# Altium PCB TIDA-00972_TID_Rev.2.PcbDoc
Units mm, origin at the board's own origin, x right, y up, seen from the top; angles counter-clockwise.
Board outline 8.12 x 16.23 mm, 2 copper layers (Top Layer, Bottom Layer), stack 1.575 mm thick; 15 components, 7 nets, 38 pads, 12 vias.
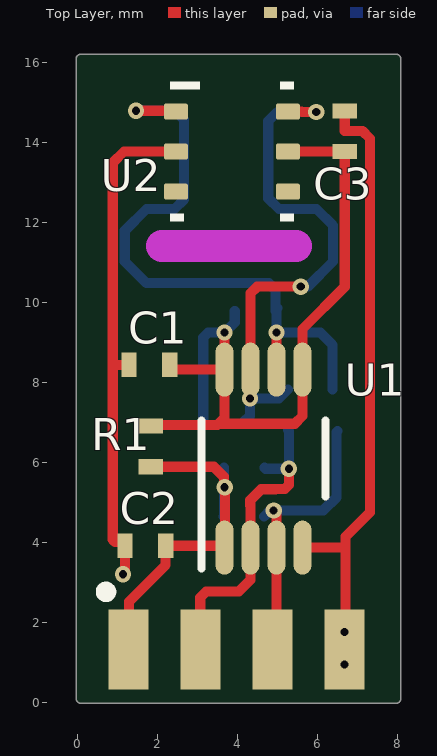
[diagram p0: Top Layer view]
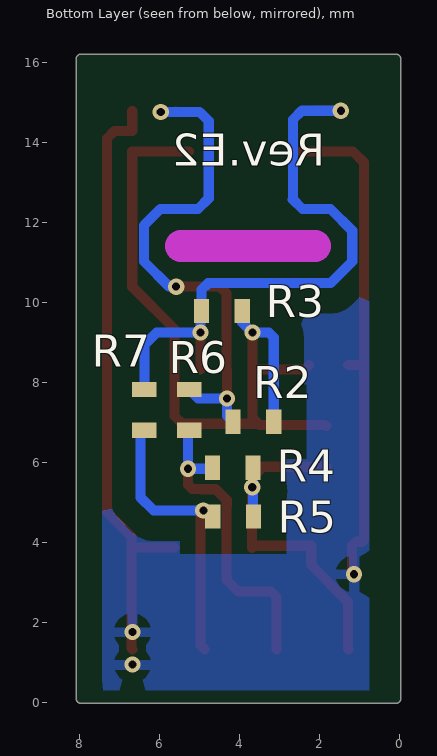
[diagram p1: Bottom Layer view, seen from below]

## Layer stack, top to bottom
Top Solder: solder mask 0.0102, Solder Resist, Dk 3.5
Top Layer: signal copper 0.0356
Dielectric1: core 1.5037, FR-4, Dk 4.8
Bottom Layer: signal copper 0.0356
Bottom Solder: solder mask 0.0102, Solder Resist, Dk 3.5

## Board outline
-0.03,0.098 -0.03,16.026 cw(c0.098,16.026) -0.027,16.051 cw(c0.098,16.076) 0.098,16.204 7.964,16.204 cw(c7.964,16.076) 8.091,16.076 cw(c7.964,16.076) 8.089,16.051 cw(c7.964,16.026) 8.091,16.026 8.091,0.098 cw(c7.964,0.098) 7.936,-0.027 0.098,-0.03 cw(c0.098,0.098)

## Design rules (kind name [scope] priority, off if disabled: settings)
AcuteAngle [All] p1: minimum=4.50000000000000E+0001 checktracksonly=FALSE
AssemblyTestPointUsage [All] p1: valid=2
Clearance Clearance_Keepouts [((IsTrack Or IsArc) And Not InPoly) And IsFree and IsKeepOut vs ((IsTrack Or IsArc) And Not InPoly) And IsFree and IsKeepOut] p1: gap=0
Clearance Clearance_BoardEdge_MountingHoles [OnCopper and InComponentClass('Mounting Holes') vs IsKeepOut] p2: gap=1.016
Clearance Clearance_BoardEdge_Poly [OnCopper and InPoly vs IsKeepOut] p3: gap=0.635
Clearance Clearance_BoardEdge [OnCopper and Not InComponentClass('Logo') and not InComponentClass('FiducialMark') and not InRegion(1000,500,4000,800) and Not IsKeepout vs IsKeepOut] p4: gap=0.4
Clearance Clearance_Poly [InPolygon] p5: gap=0.635
Clearance [All] p6: gap=0.2
ComponentClearance ComponentClearance_MountingHoles_FiducialMarks [InComponentClass('Mounting Holes') vs InComponentClass('FiducialMark')] p1: gap=1.27 collisioncheckmode=3 verticalgap=0.254 showdistances=FALSE
ComponentClearance ComponentClearance_Shunt [InComponentClass('Header') vs InComponentClass('Shunt')] p2: gap=0 collisioncheckmode=3 verticalgap=0 showdistances=FALSE
ComponentClearance ComponentClearance_Logo [InComponentClass('Logo')] p3: gap=1.27 collisioncheckmode=3 verticalgap=0.254 showdistances=FALSE
ComponentClearance ComponentClearance_ScrewToNut [(HasFootprint('NY PMS 440 0025 PH')) vs (HasFootprint('Keystone_1902C'))] p4: gap=0.127 collisioncheckmode=3 verticalgap=0.254 showdistances=FALSE
ComponentClearance ComponentClearance_MountingHoles [InComponentClass('Mounting Holes')] p5: gap=6.35 collisioncheckmode=3 verticalgap=2540 showdistances=FALSE
ComponentClearance ComponentClearance_SmallPassives [HasFootprint('0201*') or HasFootprint('0402*') or HasFootprint('0508') or HasFootprint('0603*') or HasFootprint('0612') or HasFootprint('0805*') or HasFootprint('0815*') or HasFootprint('0830*') or HasFootprint('1206*') or HasFootprint('1210*') or HasFootprint('1808*') or HasFootprint('1812*') or HasFootprint('1825*') or HasFootprint('2010*') or HasFootprint('2220*') or HasFootprint('2225*') or HasFootprint('2512*') or HasFootprint('2728*') or HasFootprint('3518*') vs HasFootprint('0201*') or HasFootprint('0402*') or HasFootprint('0508') or HasFootprint('0603*') or HasFootprint('0612') or HasFootprint('0805*') or HasFootprint('0815*') or HasFootprint('0830*') or HasFootprint('1206*') or HasFootprint('1210*') or HasFootprint('1808*') or HasFootprint('1812*') or HasFootprint('1825*') or HasFootprint('2010*') or HasFootprint('2220*') or HasFootprint('2225*') or HasFootprint('2512*') or HasFootprint('2728*') or HasFootprint('3518*')] p6: gap=0.508 collisioncheckmode=3 verticalgap=0.254 showdistances=FALSE
ComponentClearance ComponentClearance_THtoSMT [IsThruComponent vs IsSMTComponent] p7: gap=2.54 collisioncheckmode=3 verticalgap=0.762 showdistances=FALSE
ComponentClearance ComponentClearance_THtoTH [IsThruComponent vs IsThruComponent] p8: gap=3 collisioncheckmode=3 verticalgap=0.762 showdistances=FALSE
ComponentClearance [All] p9: gap=1.016 collisioncheckmode=3 verticalgap=0.254 showdistances=FALSE
DiffPairsRouting [All] p1: maxlimit=2.54 minlimit=0.254 mostfreqgap=0.254 toplayer_minwidth=0.381 toplayer_maxwidth=0.381 toplayer_prefwidth=0.381 bottomlayer_minwidth=0.381 bottomlayer_maxwidth=0.381 bottomlayer_prefwidth=0.381 maxuncoupledlength=25.4
FabricationTestPointUsage TestPointUsage [All] p1: valid=2 allowmultiple=FALSE
FabricationTestpoint Testpoint [All] p1: side=3 testpointundercomponent=TRUE minsize=1.016 maxsize=2.54 preferedsize=1.524 minholesize=0 maxholesize=1.016 preferedholesize=0.813 testpointgrid=0.025 allowsidetop=TRUE allowsidebottom=TRUE usegrid=TRUE gridtolerance=0
FanoutControl Fanout_LCC [IsLCC] p1: bgadir=Out bgaviamode=Centered fanoutstyle=Auto fanoutdirection=Alternating viagrid=0.025 // Fanout_LCC (Default Rule)
FanoutControl Fanout_BGA [IsBGA] p2: bgadir=Out bgaviamode=Centered fanoutstyle=Auto fanoutdirection=Alternating viagrid=0.025 // Fanout_BGA (Default Rule)
FanoutControl Fanout_Default [All] p4: bgadir=Out bgaviamode=Centered fanoutstyle=Auto fanoutdirection=Alternating viagrid=0.025 // Fanout_Default (Default Rule)
FanoutControl Fanout_Small [(CompPinCount < 5)] p5: bgadir=Out bgaviamode=Centered fanoutstyle=Auto fanoutdirection=OutThenIn viagrid=0.025 // Fanout_Small (Default Rule)
HoleSize [All] p1: absolutevalues=TRUE maxlimit=6.375 minlimit=0.203 maxpercent=80.000 minpercent=20.000
MinimumAnnularRing MinimumAnnularRing_ThermalPadVias [IsVia and InAnyComponent] p1: minimumring=0.025
MinimumAnnularRing [All] p2: minimumring=0.025
MinimumSolderMaskSliver MinimumSolderMaskSliver_Logo [InComponentClass('Logo') vs InComponentClass('Logo')] p1: minsoldermaskwidth=0.018
MinimumSolderMaskSliver [All] p2: minsoldermaskwidth=0.1
PlaneConnect [All] p1: planeconnectstyle=Relief reliefexpansion=0.254 reliefentries=4 reliefconductorwidth=0.254 reliefairgap=0.254
PolygonConnect [All] p1: connectstyle=Relief reliefconductorwidth=0.254 reliefentries=4 polygonreliefangle="90 Angle" airgapwidth=0.254
RoutingVias ThermalPadVias [IsVia and InAnyComponent] p1: holewidth=0.2 width=0.5 viastyle="Through Hole" minholewidth=0.2 minwidth=0.5 maxholewidth=0.33 maxwidth=0.6
RoutingVias [All] p2: holewidth=0.406 width=0.864 viastyle="Through Hole" minholewidth=0.152 minwidth=0.203 maxholewidth=1.016 maxwidth=1.651
SilkToBoardRegionClearance [Not ((IsComment or IsDesignator) And (Hide <> 'False')) and not InRegion(1000,500,4000,800)] p1:
SilkToSilkClearance SilkToSilkClearance_Pb-FreeLogo [(HasFootprint('Pb-Free_Overlay_Medium') OR HasFootprint('Pb-Free_Overlay_Small')) vs (HasFootprint('Pb-Free_Overlay_Medium') OR HasFootprint('Pb-Free_Overlay_Small'))] p1: silktosilkclearance=0
SilkToSilkClearance [All] p2: silktosilkclearance=0.102
SilkToSolderMaskClearance SilkToComonentPadClearance [IsPad and InAnycomponent] p1: minsilkscreentomaskgap=0.127 clearancetoexposedcopper=TRUE
SilkToSolderMaskClearance "Silk to Solder Mask Opening" [All] p2: minsilkscreentomaskgap=0.102 clearancetoexposedcopper=FALSE
SolderMaskExpansion [All] p1: expansion=0.05
UnpouredPolygon [All] p1: allowunpoured=FALSE
Width [All] p1: maxlimit=2.54 minlimit=0.152 preferedwidth=0.254 checkconnectedcopper=TRUE
14 further rules are at their usual default settings.

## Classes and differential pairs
component class TIDA-00972_TID_Hardware: ZZ2 ZZ3 ZZ4
component class AssemblyNote: ZZ2 ZZ3 ZZ4
component class TIDA-00972_Rev.2: C1 C2 C3 R1 R2 R3 R4 R5 R6 R7 U1 U2

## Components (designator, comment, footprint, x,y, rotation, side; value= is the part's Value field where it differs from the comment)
C1 "885012105016" 0402S 1.803,8.433 r180 top
C2 "885012105016" 0402S 1.702,3.912 r180 top
C3 "885012105016" 0402S 6.686,14.274 r90 top
R1 "RC0402JR-070RL" 0402S 1.836,6.395 r270 top
R2 "CRCW04025K90FKED" 0402S 3.658,7.01 r180 bottom
R3 "CRCW04025K90FKED" 0402S 4.445,9.779 r180 bottom
R4 "CRCW04022K40JNED" 0402S 4.173,5.862 r180 bottom
R5 "CRCW04022K40JNED" 0402S 4.163,4.643 r180 bottom
R6 "RC0402JR-070RL" 0402S 5.265,7.31 r270 bottom
R7 "RC0402JR-070RL" 0402S 6.383,7.31 r270 bottom
U1 "TCA9517DGKR" DGK0008A_N 4.655,6.091 r90 top
U2 "HDC1080DMBR" DMB0006A 3.866,13.766 r0 top
ZZ2 "These assemblies are ESD sensitive, ESD precautions shall be observed." AssemblyNote -20.086,96.217 r0 top
ZZ3 "These assemblies must be clean and free from flux and all contaminants. Use of no clean flux is not acceptable." AssemblyNote -20.086,93.968 r0 top
ZZ4 "These assemblies must comply with workmanship standards IPC-A-610 Class 2, unless otherwise specified." AssemblyNote -20.086,91.718 r0 top

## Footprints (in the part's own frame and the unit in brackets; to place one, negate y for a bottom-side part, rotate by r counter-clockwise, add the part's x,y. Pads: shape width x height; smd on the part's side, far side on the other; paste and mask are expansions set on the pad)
0402S [mil] "Based on C0402S footprint from PADS legacy"
  rect 15x24 smd: 1(-20,0) 2(20,0)
  body extent -22,-12 22,12, height 24
AssemblyNote [mm] "Assembly Note"
DGK0008A_N [mm] "TSOP, 8-Leads, Body 3x3mm, Pitch 0.65mm, IPC Medium Density"
  oval 1.35x0.45 smd: 1(-2.225,0.975) 2(-2.225,0.325) 3(-2.225,-0.325) 4(-2.225,-0.975) 5(2.225,-0.975) 6(2.225,-0.325) 7(2.225,0.325) 8(2.225,0.975)
  silkscreen extent -2.75,-1.55 0.95,1.55, body extent -2.45,-1.5 2.45,1.5, height 0.96
DMB0006A [mm] "TI"
  rrect25% 0.6x0.4 smd: 1(-1.4,1) 2(-1.4,0) 3(-1.4,-1) 4(1.4,-1) 5(1.4,0) 6(1.4,1)
  silkscreen extent -1.55,-1.75 1.55,1.75, body extent -1.5,-1.5 1.5,1.5, height 0.81

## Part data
C1 C2 C3: "CAP, CERM, 0.1 μF, 16 V, +/- 20%, X5R, 0402"
R1 R6 R7: "RES, 0, 5%, 0.063 W, 0402"
R2 R3: "RES, 5.90 k, 1%, 0.063 W, 0402"
R4 R5: "RES, 2.4 k, 5%, 0.063 W, 0402"
U1: "LEVEL-TRANSLATING I2C BUS REPEATER, DGK0008A"
U2: "Low Power, High Accuracy Digital Humidity Sensor with Temperature Sensor, DMB0006A"
ZZ2 ZZ3 ZZ4: library part AssemblyNote

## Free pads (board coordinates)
  rect 1x2 smd: 0(1.277,1.321) 0(3.077,1.321) 0(4.877,1.321) 0(6.677,1.321)

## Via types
v1: diameter 0.406, hole 0.203, Top Layer to Bottom Layer, 12 vias

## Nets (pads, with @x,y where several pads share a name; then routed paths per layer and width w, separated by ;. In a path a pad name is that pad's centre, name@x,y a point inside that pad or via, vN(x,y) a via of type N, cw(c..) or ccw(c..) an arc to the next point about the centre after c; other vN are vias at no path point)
GND: C1.2 C2.2 C3.2 pad.0@6.677,1.321 U1.4 U2.2 | length 27.9
  Top Layer w0.254: v1(1.143,3.2) 1.194,3.251 C2.2 1.092,4.013 0.94,4.013 0.889,4.064 0.889,8.433 ; C1.2 0.889,8.433 ; U2.2 1.167,13.766 0.889,13.487 0.889,8.433 ; U1.4 6.701,3.866 6.706,3.861 ; pad.0@6.677,1.321 6.706,1.35 6.706,3.861 ; C3.2 6.686,14.283 7.126,14.283 7.318,14.092 7.318,4.747 6.706,4.136 6.706,3.861
  other v1: 6.68,0.94 6.68,1.753
SCLA: pad.0@3.077,1.321 R4.1 R6.2 U1.2 | length 7.9
  Top Layer w0.254: pad.0@3.077,1.321 3.077,2.62 3.226,2.769 4.039,2.769 4.33,3.06 U1.2 4.33,4.917 4.325,4.922 4.325,5.049 4.601,5.325 4.96,5.325 4.963,5.329 5.189,5.329 5.29,5.43 v1(5.29,5.837)
  Bottom Layer w0.254: R4.1 4.706,5.837 v1(5.29,5.837) 5.29,6.776 R6.2
SCLB: R2.1 R6.1 U1.7 U2.6 | length 13.1
  Top Layer w0.254: v1(4.318,7.595) 4.318,8.303 U1.7 4.33,10.223 4.496,10.389 v1(5.588,10.389) ; 5.602,14.771 5.617,14.756 v1(5.975,14.756)
  Bottom Layer w0.254: R2.1 4.318,7.163 v1(4.318,7.595) 5.042,7.595 R6.1 ; v1(5.588,10.389) 5.763,10.389 6.394,11.02 6.394,11.92 5.983,12.331 5.043,12.331 4.775,12.598 4.775,14.529 5.003,14.756 v1(5.975,14.756)
SDAA: pad.0@4.877,1.321 R5.1 R7.2 U1.3 | length 7.2
  Top Layer w0.254: pad.0@4.877,1.321 4.98,1.424 U1.3 4.98,4.724 v1(4.909,4.795)
  Bottom Layer w0.254: R5.1 4.824,4.795 v1(4.909,4.795) 6.154,4.795 6.484,5.125 6.484,6.751 R7.2@6.51,6.776
SDAB: R3.1 R7.1 U1.6 U2.1 | length 15.3
  Top Layer w0.254: v1(1.472,14.787) 2.113,14.787 ; v1(4.978,9.241) 4.978,8.318 U1.6
  Bottom Layer w0.254: v1(1.472,14.787) 2.445,14.787 2.666,14.566 2.666,12.578 2.673,12.572 2.431,12.331 1.73,12.331 1.187,11.787 1.187,11.02 1.73,10.477 4.789,10.477 4.953,10.312 R3.1 ; R3.1@5.004,9.855 4.978,9.83 v1(4.978,9.241) 6.076,9.241 6.383,8.934 R7.1
VCCA: C2.1 pad.0@1.277,1.321 R1.2 R4.2 R5.2 U1.1 | length 9.4
  Top Layer w0.254: pad.0@1.277,1.321 1.295,1.339 1.295,2.515 2.21,3.429 C2.1 3.634,3.912 U1.1 3.69,3.856 3.69,5.252 3.665,5.278 3.665,5.639 3.416,5.887 R1.2
  Bottom Layer w0.254: R5.2 3.665,4.652 3.665,5.278 R4.2
  other v1: 3.685,5.375
VCCB: C1.1 C3.1 R1.1 R2.2 R3.2 U1.5 U1.8 U2.5 | length 19.5
  Top Layer w0.254: R1.1 1.867,6.934 3.505,6.934 3.531,6.96 ; C1.1@2.268,8.427 2.38,8.316 U1.8 ; v1(3.683,9.241) 3.683,7.112 3.531,6.96 ; U2.5 C3.1 6.686,10.385 5.63,9.329 U1.5 5.63,7.155 5.436,6.96 3.531,6.96
  Bottom Layer w0.254: R2.2 3.15,9.119 3.272,9.241 v1(3.683,9.241) 3.937,9.495 R3.2
pads on no net: U2.3 U2.4

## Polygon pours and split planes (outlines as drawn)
GND on Bottom Layer "Top Layer-No Net" (solid, remove dead copper, pour order 3): 7.442,0.279 7.417,0.305 0.762,0.305 0.762,10.595 1.187,11.02 1.208,10.998 7.087,10.998 7.391,10.998 7.442,10.947 7.442,0.305

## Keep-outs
Keep-Out Layer:
  lines w0.8: 2.114,11.404 5.467,11.404
  text ".Layer_Name" at -10.129,-22.848 h1.52

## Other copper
Top Layer:
  text ".Layer_Name" at -10.129,-22.848 h1.52
Bottom Layer:
  text ".Layer_Name" at -10.129,-22.848 h1.52

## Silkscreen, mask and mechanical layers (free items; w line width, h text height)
Top Overlay:
  lines w0.254: 0.842,2.719 cw(c0.719,2.76) 0.849,2.76
  text ".Layer_Name" at -10.129,-22.848 h1.52
Bottom Overlay:
  text "Rev.E2" at 1.86,13.41 h0.8
  text ".Layer_Name" at -10.129,-22.848 h1.52
Top Paste:
  text ".Layer_Name" at -10.129,-22.848 h1.52
Bottom Paste:
  text ".Layer_Name" at -10.129,-22.848 h1.52
Top Solder:
  text ".Layer_Name" at -10.129,-22.848 h1.52
  text ".Layer_Name" at -10.129,-22.848 h1.52
Bottom Solder:
  text ".Layer_Name" at -10.129,-22.848 h1.52
Drill Guide:
  text ".Layer_Name" at -10.129,-22.848 h1.52
M1 Board Outline:
  lines w0.254: 0.098,16.026 0.098,0.098 2.064,0.098 5.997,0.1 7.964,0.101 ; 0.098,16.076 7.964,16.076 ; 7.964,0.098 7.964,16.026
  text ".Layer_Name" at -10.129,-22.848 h1.52
M2 Board Dimensions:
  rectangle: -24.785,-8.027 -21.61,-4.852
  rectangle: -21.61,-11.202 -12.085,-8.027
  lines w0.178: -24.785,-8.027 0.615,-8.027 ; -24.785,-4.852 -24.785,-11.202 0.615,-11.202 0.615,-4.852 ; -21.61,-11.202 -21.61,-4.852 ; -18.435,-11.202 -18.435,-4.852 ; -12.085,-11.202 -12.085,-4.852 ; -5.735,-11.202 -5.735,-4.852
  text ".Layer_Name" at -10.129,-22.848 h1.52
M3 3D STEP Top:
  text ".Layer_Name" at -10.129,-22.848 h1.52
M4 3D STEP Bottom:
  text ".Layer_Name" at -10.129,-22.848 h1.52
M5 Assembly Top:
  lines w0.254: -32.202,-24.669 135.438,-24.669 ; -32.202,-19.504 135.489,-19.504 ; -32.202,-14.339 -32.202,-29.833 69.525,-29.833 135.489,-29.833 135.489,-14.339 -32.189,-14.339 -32.189,-29.833 7.829,-29.833 ; 30.409,-29.833 30.409,-14.339 ; 62.591,-19.504 62.591,-14.339 ; 83.927,-19.504 83.927,-14.339 ; 99.726,-29.998 99.726,-24.847
  text "COMPONENTS MARKED 'DNP' SHOULD NOT BE POPULATED." at 4.514,-9.132 h1.52
  text "ASSEMBLY VARIANT:" at 4.501,-12.066 h1.52
  text ".VariantName" at 30.816,-12.066 h1.52
  text "PCB VIEWED FROM TOP SIDE" at -30.589,-17.696 h1.52
  text "BOARD #:" at 32.314,-17.696 h1.52
  text ".PRJ_Number" at 46.17,-17.696 h1.52
  text "REV:" at 67.62,-17.696 h1.52
  text ".PCB_Rev" at 75.024,-17.696 h1.52
  text "SVN REV:" at 88.906,-17.696 h1.52
  text ".VersionControl_RevNumber" at 101.758,-17.696 h1.52
  text "TID #:" at 32.314,-22.861 h1.52
  text ".TID" at 46.17,-22.861 h1.52
  text "PLOT NAME =" at -30.589,-28.077 h1.52
  text ".plot_File_Name" at -10.129,-28.077 h1.52
  text "GENERATED    :" at 32.365,-28.077 h1.52
  text ".Print_Date" at 54.45,-28.077 h1.52
  text ".Print_Time" at 72.967,-28.077 h1.52
  text "TEXAS INSTRUMENTS" at 105.085,-28.077 h1.52
M6 Assembly Bottom:
  lines w0.254: -32.214,-19.517 135.476,-19.517 ; -32.164,-24.681 135.476,-24.681 ; 3.549,-30.011 3.549,-24.859 ; 19.348,-19.517 19.348,-14.352 ; 40.684,-19.517 40.684,-14.352 ; 72.865,-29.846 72.865,-14.352 ; 95.446,-29.846 135.464,-29.846 135.464,-14.352 -32.214,-14.352 -32.214,-29.846 33.749,-29.846 135.476,-29.846 135.476,-14.352
  text "COMPONENTS MARKED 'DNP' SHOULD NOT BE POPULATED." at 130.206,-9.12 h1.52
  text ".VariantName" at 103.688,-12.066 h1.52
  text "ASSEMBLY VARIANT:" at 130.079,-12.066 h1.52
  text ".VersionControl_RevNumber" at 1.517,-17.709 h1.52
  text "SVN REV:" at 14.369,-17.709 h1.52
  text ".PCB_Rev" at 28.25,-17.709 h1.52
  text "REV:" at 35.654,-17.709 h1.52
  text ".PRJ_Number" at 57.105,-17.709 h1.52
  text "BOARD #:" at 70.96,-17.709 h1.52
  text "PCB VIEWED FROM BOTTOM SIDE" at 133.864,-17.709 h1.52
  text ".TID" at 57.105,-22.874 h1.52
  text "TID #:" at 70.96,-22.874 h1.52
  text "TEXAS INSTRUMENTS" at -1.811,-28.089 h1.52
  text ".Print_Time" at 30.308,-28.089 h1.52
  text ".Print_Date" at 48.824,-28.089 h1.52
  text "GENERATED    :" at 70.91,-28.089 h1.52
  text ".plot_File_Name" at 113.404,-28.089 h1.52
  text "PLOT NAME =" at 133.864,-28.089 h1.52
M10 Fab Notes:
  drawing of 173 lines, arcs and shapes, not listed
  text "DESIGN INFORMATION" at 289.591,156.463 h1.52
  text "MIN. TRACK WIDTH:" at 273.22,151.891 h1.52
  text "8" at 301.064,151.891 h1.52
  text "MIL" at 304.995,151.891 h1.52
  text "MIN. CLEARANCE:" at 273.22,148.538 h1.52
  text "0.2" at 299.54,148.538 h1.52
  text "mm" at 304.995,148.538 h1.52
  text "MIN. VIA PAD SIZE:" at 273.22,145.185 h1.52
  text "24" at 300.302,145.185 h1.52
  text "MIL" at 304.995,145.185 h1.52
  text "0.05mm (2MIL)" at 290.873,141.586 h1.52
  text "MINIMUM ANNULAR RING" at 264.857,141.477 h1.52
  text "EXTERNAL" at 308.856,141.477 h1.52
  text "PER" at 269.937,138.48 h1.52
  text "IPC-D-275 CLASS 2 LEVEL C" at 275.525,138.48 h1.52
  text "MIL, HOLES" at 313.326,135.628 h1.52
  text "+/-" at 303.358,135.61 h1.52
  text "+/-" at 325.049,135.61 h1.52
  text "REGISTRATION TOLERANCES:" at 264.857,135.483 h1.52
  text "METAL" at 295.331,135.483 h1.52
  text "5" at 309.967,135.483 h1.52
  text "3" at 331.125,135.483 h1.52
  text "MIL" at 334.078,135.483 h1.52
  text "+/-" at 325.049,132.612 h1.52
  text "HOLE SIZE TOLERANCE (UNLESS OTHERWISE SPECIFIED):" at 264.857,132.485 h1.52
  text "3" at 331.125,132.485 h1.52
  text "MIL" at 334.078,132.485 h1.52
  text "MATERIAL:" at 262.958,127.165 h1.52
  text "FR-4 High Tg" at 288.014,123.601 h1.52
  text "FR-408" at 273.651,123.383 h1.52
  text "OTHER" at 311.447,123.383 h1.52
  text "X" at 284.079,123.291 h1.52
  text "62 MIL (1.6mm) +/-10%" at 281.782,119.25 h1.52
  text "THICKNESS:" at 264.857,119.141 h1.52
  text "X" at 278.527,119.141 h1.52
  text "OTHER" at 314.418,119.141 h1.52
  text "TOLERANCE:" at 264.857,115.128 h1.52
  text "X" at 286.175,115.128 h1.52
  text "ANSI IPC-6012 TYPE 3 CLASS 2" at 290.924,115.128 h1.52
  text "OTHER +/-" at 290.923,111.166 h1.52
  text "BOW & TWIST:" at 264.857,107.178 h1.52
  text "X" at 286.175,107.178 h1.52
  text "ANSI IPC-6012 TYPE 3 CLASS 2" at 290.924,107.178 h1.52
  text "OTHER +/-" at 290.923,103.152 h1.52
  text "DRILLING:" at 262.958,99.634 h1.52
  text "REFERENCE:" at 264.857,96.662 h1.52
  text "X" at 281.322,96.662 h1.52
  text "AS SHOWN" at 286.072,96.662 h1.52
  text "X" at 304.208,96.662 h1.52
  text "NC_DRILL FILES" at 307.687,96.662 h1.52
  text "PTH MIN COPPER THICKNESS:" at 264.857,92.649 h1.52
  text "X" at 299.153,92.649 h1.52
  text "1MIL" at 302.633,92.649 h1.52
  text "OTHER" at 315.257,92.649 h1.52
  text "BOARD FINISH:" at 262.958,88.61 h1.52
  text "SILKSCREEN:" at 266.901,85.613 h1.52
  text "X" at 291,85.613 h1.52
  text "TOP" at 294.2,85.613 h1.52
  text "X" at 303.954,85.613 h1.52
  text "BOTTOM" at 307.179,85.613 h1.52
  text "SILKSCREEN COLOR:" at 266.901,81.371 h1.52
  text "X" at 290.973,81.371 h1.52
  text "WHITE" at 294.2,81.371 h1.52
  text "OTHER" at 307.179,81.371 h1.52
  text "X" at 294.301,77.328 h1.52
  text "GREEN" at 297.527,77.328 h1.52
  text "OTHER" at 313.225,77.328 h1.52
  text "SOLDER RESIST COLOR:" at 266.901,77.053 h1.52
  text "X" at 294.301,73.01 h1.52
  text "MATTE" at 297.527,73.01 h1.52
  text "SEMI-GLOSS" at 313.213,72.994 h1.52
  text "IMMERSION GOLD (ENIG)" at 289.907,68.221 h1.52
  text "ENEPIG" at 323.881,68.138 h1.52
  text "SURFACE FINISH:" at 262.958,68.113 h1.52
  text "X" at 285.159,68.113 h1.52
  text "IMM. TIN/SILVER OR EQUIV" at 271.328,64.125 h1.52
  text "OTHER" at 307.687,64.125 h1.52
  text "ARRAY/PANEL:" at 262.958,59.578 h1.52
  text "CUT AND TRIM PER M1 BOARD OUTLINE" at 289.907,59.469 h1.52
  text "N.C. ROUTE" at 289.907,55.616 h1.52
  text "X" at 307.154,55.616 h1.52
  text "V. SCORE" at 311.904,55.616 h1.52
  text "CERTIFICATION:" at 262.958,52.136 h1.52
  text "MATERIALS AND WORKMANSHIP FOR ALL PCBS" at 281.373,52.136 h1.52
  text "TO MEET OR EXCEED THE REQUIREMENTS OF:" at 281.373,49.647 h1.52
  text "X" at 271.886,46.18 h1.52
  text "ANSI IPC-A-600F CLASS ->" at 275.417,46.18 h1.52
  text "X" at 317.049,46.18 h1.52
  text "2" at 320.07,46.18 h1.52
  text "1" at 312.069,46.142 h1.52
  text "3" at 329.062,46.142 h1.52
  text "X" at 292.563,42.128 h1.52
  text "RoHS" at 296.042,42.128 h1.52
  text "OTHER" at 312.409,42.128 h1.52
  text "PER ORDER" at 322.495,42.128 h1.52
  text "ALL BOARDS MUST MEET OR EXCEED UL94-V0 REQUIREMENTS." at 263.658,37.921 h1.52
  text "PCB MUST BEAR THE UL94V-0 UL REGISTERED MATERIAL ID NUMBER" at 263.658,34.873 h1.52
  text "ADDITIONAL REQUIREMENTS:" at 262.958,30.47 h1.52
  text "MICROSECTION:" at 264.857,27.549 h1.52
  text "YES" at 287.863,27.549 h1.52
  text "REQUIRED" at 309.745,23.583 h1.52
  text "BARE BOARD ELEC. TEST:" at 264.857,23.51 h1.52
  text "NONE" at 298.023,23.51 h1.52
  text "X" at 306.519,23.51 h1.52
  text "PER ORDER" at 324.782,23.51 h1.52
  text ".Layer_Name" at -10.129,-22.848 h1.52
M11 Gerber Information:
  lines w0.254: -32.202,-24.669 135.438,-24.669 ; -32.202,-19.504 135.489,-19.504 ; -32.202,-14.339 -32.202,-29.833 69.525,-29.833 135.489,-29.833 135.489,-14.339 -32.189,-14.339 -32.189,-29.833 7.829,-29.833 ; 30.409,-29.833 30.409,-14.339 ; 62.591,-19.504 62.591,-14.339 ; 83.927,-19.504 83.927,-14.339 ; 99.726,-29.998 99.726,-24.847
  text "ALL ARTWORK VIEWED FROM TOP SIDE" at -30.589,-17.696 h1.52
  text "BOARD #:" at 32.314,-17.696 h1.52
  text ".PRJ_Number" at 46.17,-17.696 h1.52
  text "REV:" at 67.62,-17.696 h1.52
  text ".PCB_Rev" at 75.024,-17.696 h1.52
  text "SVN REV:" at 88.906,-17.696 h1.52
  text ".VersionControl_RevNumber" at 101.758,-17.696 h1.52
  text "LAYER NAME =" at -30.589,-22.848 h1.52
  text "TID #:" at 32.314,-22.861 h1.52
  text ".TID" at 46.17,-22.861 h1.52
  text "PLOT NAME =" at -30.589,-28.077 h1.52
  text ".plot_File_Name" at -10.129,-28.077 h1.52
  text "GENERATED    :" at 32.365,-28.077 h1.52
  text ".Print_Date" at 54.45,-28.077 h1.52
  text ".Print_Time" at 72.967,-28.077 h1.52
  text "TEXAS INSTRUMENTS" at 105.085,-28.077 h1.52
M12 Stackup:
  drawing of 191 lines, arcs and shapes, not listed
  text "Layer" at 223.896,197.84 h1.52
  text "Name" at 234.308,197.84 h1.52
  text "Material" at 257.923,197.84 h1.52
  text "Thickness" at 279.761,197.84 h1.52
  text "Constant" at 296.267,197.84 h1.52
  text "Board Layer Stack" at 310.741,197.84 h1.52
  text "1" at 223.896,194.792 h1.52
  text "Top Overlay" at 234.308,194.792 h1.52
  text "2" at 223.896,191.744 h1.52
  text "Top Solder" at 234.308,191.744 h1.52
  text "Solder Resist" at 257.923,191.744 h1.52
  text "0.40mil" at 279.761,191.744 h1.52
  text "3.5" at 296.267,191.744 h1.52
  text "3" at 223.896,188.696 h1.52
  text "Top Layer" at 234.308,188.696 h1.52
  text "Copper" at 257.923,188.696 h1.52
  text "1.40mil" at 279.761,188.696 h1.52
  text "4" at 223.896,185.648 h1.52
  text "Dielectric1" at 234.308,185.648 h1.52
  text "FR-4" at 257.923,185.648 h1.52
  text "59.20mil" at 279.761,185.648 h1.52
  text "4.8" at 296.267,185.648 h1.52
  text "5" at 223.896,182.6 h1.52
  text "Bottom Layer" at 234.308,182.6 h1.52
  text "Copper" at 257.923,182.6 h1.52
  text "1.40mil" at 279.761,182.6 h1.52
  text "6" at 223.896,179.552 h1.52
  text "Bottom Solder" at 234.308,179.552 h1.52
  text "Solder Resist" at 257.923,179.552 h1.52
  text "0.40mil" at 279.761,179.552 h1.52
  text "3.5" at 296.267,179.552 h1.52
  text "7" at 223.896,176.504 h1.52
  text "Bottom Overlay" at 234.308,176.504 h1.52
  text ".Layer_Name" at -10.129,-22.848 h1.52
M13 Component Bodies Top:
  text ".Layer_Name" at -10.129,-22.848 h1.52
M14 Component Bodies Bottom:
  text ".Layer_Name" at -10.129,-22.848 h1.52
M15 Courtyards Top:
  text ".Layer_Name" at -10.129,-22.848 h1.52
M16 Courtyards Bottom:
  text ".Layer_Name" at -10.129,-22.848 h1.52
Drill Drawing:
  lines w0.025: 115.858,81.47 116.122,81.47 116.122,81.206 116.65,81.206 116.65,81.47 116.913,81.47 116.913,81.998 116.65,81.998 116.65,82.261 116.122,82.261 116.122,81.998 115.858,81.998 115.858,81.47
  lines w0.305: 114.407,80.257 165.946,80.257 ; 114.407,83.422 165.946,83.422 ; 123.25,77.091 123.25,86.588 ; 131.941,77.091 131.941,86.588 ; 148.368,77.091 148.368,86.588 ; 155.209,77.091 155.209,86.588 ; 114.407,77.091 165.946,77.091 165.946,86.588 114.407,86.588 114.407,77.091
  text "Symbol" at 116.306,84.372 h1.83
  text "Quantity" at 124.199,84.372 h1.83
  text "Finished Hole Size" at 132.891,84.372 h1.83
  text "Plated" at 149.318,84.372 h1.83
  text "Hole Type" at 156.159,84.372 h1.83
  text "12" at 124.199,81.206 h1.52
  text "8.00mil (0.203mm)" at 132.891,81.206 h1.52
  text "PTH" at 149.318,81.206 h1.52
  text "Round" at 156.159,81.206 h1.52
  text "12 Total" at 124.199,78.041 h1.52
  text ".Layer_Name" at -10.129,-22.848 h1.52

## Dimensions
0.223,-0.74 to 7.841,-0.721 on Top Layer
8.426,15.952 to 8.467,0.23 on Top Layer
-24.785,-11.202 to 0.615,-11.202 on M2 Board Dimensions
